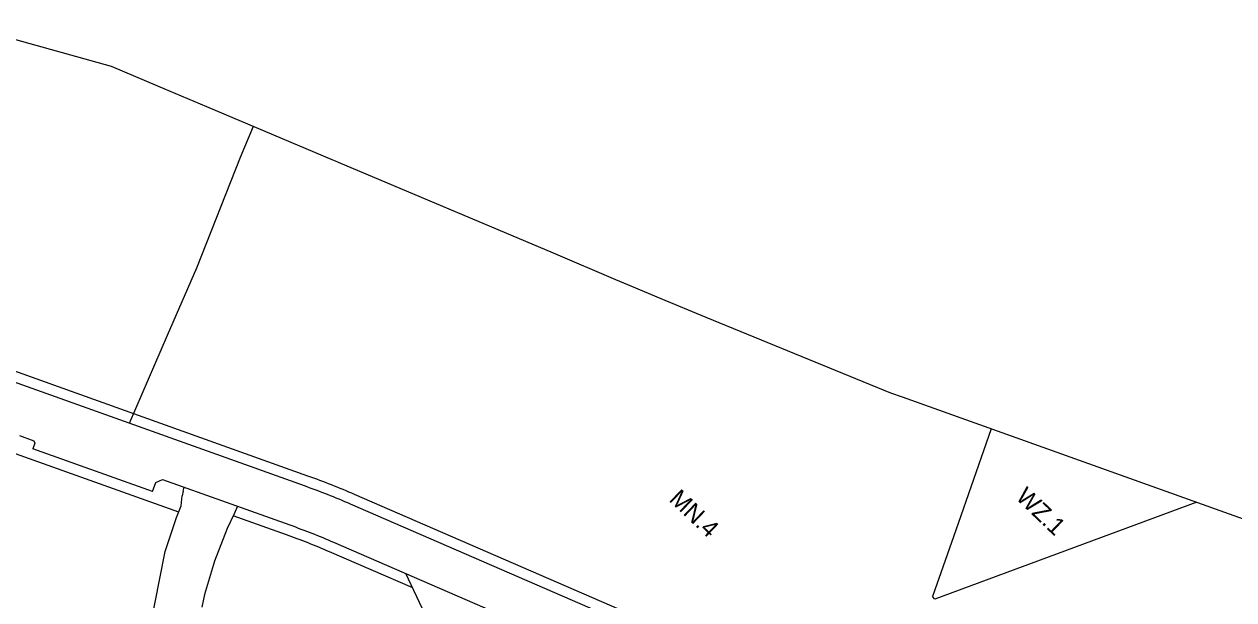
# Model space of a CAD drawing. Extents: x 7420063 to 7422255, y 5550978 to 5552824.
# Drawn here: x 7421663.8 to 7422010.7, y 5551603.9 to 5551768.9 of the extents above; entities that cross this region are included whole.
import ezdxf

# ---------------------------------------------------------------- set-up
doc = ezdxf.new("R2010")
doc.units = 0
for name, color, linetype in [('linie_rozgraniczajace', 7, 'Continuous'), ('linie_zabudowy_nieprzekraczalne', 7, 'Continuous'), ('oznaczenia_przeznaczen', 7, 'Continuous')]:
    doc.layers.add(name, color=color, linetype=linetype)

msp = doc.modelspace()

# ---------------------------------------------------------------- linework, layer by layer
at = {"layer": 'linie_rozgraniczajace'}
for p, q in [((7421662.4, 5551651.03), (7421666.5, 5551649.48)), ((7421666.8, 5551648.85), (7421666.21, 5551647.2)), ((7421666.5, 5551649.48), (7421666.8, 5551648.85)), ((7421700.58, 5551634.92), (7421666.21, 5551647.2)), ((7421701.51, 5551637.51), (7421703.43, 5551638.41)), ((7421700.58, 5551634.92), (7421701.51, 5551637.51)), ((7421709.36, 5551635.06), (7421709.06, 5551633.71)), ((7421709.36, 5551635.06), (7421709.62, 5551636.2))]:
    msp.add_line(p, q, dxfattribs=at)
for points in [[(7421645.39, 5551768.93), (7421688.68, 5551756.92), (7421705.14, 5551749.96), (7421708.83, 5551748.4), (7421716.05, 5551745.35), (7421752.03, 5551730.14), (7421752.95, 5551729.75), (7421753.87, 5551729.36), (7421815.46, 5551703.33), (7421833.38, 5551695.75), (7421837.99, 5551693.81), (7421846.36, 5551690.27), (7421859.31, 5551684.96), (7421912.21, 5551663.28)], [(7421693.94, 5551654.55), (7421704.9, 5551679.78), (7421713.29, 5551699.1), (7421725.85, 5551730.85), (7421729.54, 5551739.65)], [(7421636.71, 5551674.99), (7421744.05, 5551636.64), (7421744.88, 5551636.34), (7421745.72, 5551636.04), (7421746.55, 5551635.73), (7421747.39, 5551635.42), (7421748.22, 5551635.11), (7421749.05, 5551634.79), (7421749.88, 5551634.47), (7421750.71, 5551634.14), (7421751.53, 5551633.81), (7421752.36, 5551633.48), (7421753.18, 5551633.15), (7421754, 5551632.81), (7421754.83, 5551632.47), (7421755.65, 5551632.12), (7421756.46, 5551631.77), (7421757.27, 5551631.42), (7421848.47, 5551591.89)], [(7421912.21, 5551663.28), (7421915.61, 5551662.07), (7422019.81, 5551624.84), (7422040.16, 5551617.57)], [(7421941.15, 5551652.94), (7421931.01, 5551623.85), (7421924.26, 5551604.89)], [(7421703.43, 5551638.41), (7421740, 5551625.35), (7421740.8, 5551625.06), (7421741.59, 5551624.77), (7421742.38, 5551624.48), (7421743.16, 5551624.19), (7421743.95, 5551623.89), (7421744.73, 5551623.59), (7421745.52, 5551623.29), (7421746.3, 5551622.98), (7421747.08, 5551622.67), (7421747.86, 5551622.36), (7421748.64, 5551622.04), (7421749.41, 5551621.72), (7421750.19, 5551621.4), (7421750.96, 5551621.07), (7421751.74, 5551620.74), (7421752.51, 5551620.41), (7421843.68, 5551580.89)], [(7421660.29, 5551379.47), (7421668.57, 5551424.32), (7421669.22, 5551427.87), (7421670.86, 5551436.29), (7421673.08, 5551448.75), (7421677.58, 5551473.19), (7421681.83, 5551495.53), (7421686.41, 5551523.87), (7421690.51, 5551546.6), (7421693.51, 5551563.62), (7421699.84, 5551595.51), (7421704.25, 5551617.7), (7421707.49, 5551627.54), (7421708.84, 5551630.86), (7421709.06, 5551633.71)], [(7422000.05, 5551631.9), (7421924.92, 5551604.08), (7421924.26, 5551604.89)], [(7421724.97, 5551630.72), (7421724.02, 5551628.59), (7421721.95, 5551624.32)], [(7421721.95, 5551624.32), (7421720.13, 5551619.66), (7421718.32, 5551615), (7421716.89, 5551610.21), (7421715.46, 5551605.42), (7421714.69, 5551601.79)], [(7421778.71, 5551599.88), (7421773.26, 5551611.41)]]:
    msp.add_lwpolyline(points, dxfattribs=at)
at = {"layer": 'linie_zabudowy_nieprzekraczalne'}
for points in [[(7421637.71, 5551677.82), (7421745.06, 5551639.47), (7421745.9, 5551639.16), (7421746.75, 5551638.86), (7421747.6, 5551638.54), (7421748.44, 5551638.23), (7421749.29, 5551637.91), (7421750.13, 5551637.59), (7421750.97, 5551637.26), (7421751.81, 5551636.93), (7421752.65, 5551636.6), (7421753.48, 5551636.26), (7421754.32, 5551635.92), (7421755.15, 5551635.58), (7421755.98, 5551635.23), (7421756.82, 5551634.88), (7421757.65, 5551634.53), (7421758.46, 5551634.18), (7421849.66, 5551594.64)], [(7421708.1, 5551629.05), (7421657.25, 5551647.22)], [(7421775.2, 5551607.3), (7421751.32, 5551617.65), (7421750.55, 5551617.98), (7421749.79, 5551618.31), (7421749.03, 5551618.63), (7421748.27, 5551618.95), (7421747.5, 5551619.26), (7421746.73, 5551619.57), (7421745.97, 5551619.88), (7421745.2, 5551620.19), (7421744.43, 5551620.49), (7421743.65, 5551620.79), (7421742.88, 5551621.09), (7421742.11, 5551621.38), (7421741.33, 5551621.67), (7421740.56, 5551621.96), (7421739.78, 5551622.24), (7421738.99, 5551622.52), (7421723.72, 5551627.98)]]:
    msp.add_lwpolyline(points, dxfattribs=at)

# ---------------------------------------------------------------- texts
at = {"layer": 'oznaczenia_przeznaczen'}
for s, p in [('MN.4', (7421848.48, 5551632.42)), ('WZ.1', (7421947.89, 5551633.01))]:
    msp.add_text(s, height=5, rotation=316.2133, dxfattribs=at).set_placement(p)

doc.saveas('drawing.dxf')
